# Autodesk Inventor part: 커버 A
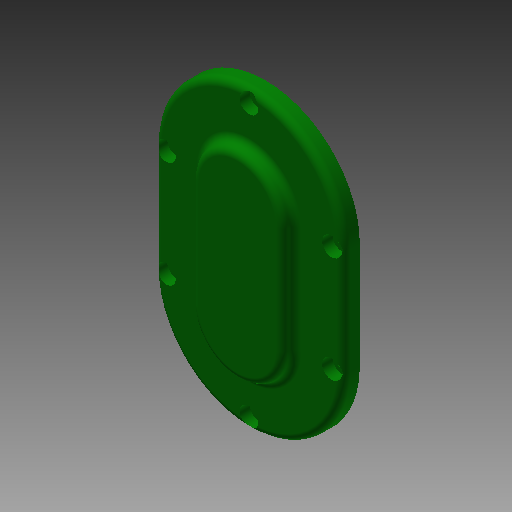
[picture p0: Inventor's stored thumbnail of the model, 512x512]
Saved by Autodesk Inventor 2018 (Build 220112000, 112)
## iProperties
Created: 2020-04
Part Number: 커버 A
Material: 알루미늄 6061
Document SubType Name: Modeling
Designer: mduedu
Density: 2.71 g/cm^3
Mass: 189.426 g
Surface Area: 209.668 cm^2
Volume: 69.8987 cm^3
Appearance: 진녹색
Author: mduedu
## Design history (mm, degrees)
sketch "스케치1"
  geometry: L1 (-40, 0)-(-40, -45); L2 (40, 0)-(40, -45); A1 r 40 centre (0, 0) between (40, 0) and (-40, 0); A2 r 40 centre (0, -45) between (-40, -45) and (40, -45); 1 further point
  constraints: 4 end point, 4 point on circle, 4 tangent, 2 centre point, 1 coincident, 1 equal radius, 1 vertical alignment
  dimensions: "d0" = 80 diameter of A1; "d31" = 45 distance of point (0, 0) A2.centre
extrude "돌출1" new body sketch "스케치1" distance "d1" = 7; taper "d2" = 0 deg
fillet "모깎기2" dims "d7" = 3
sketch "스케치4"
  geometry: L1 (30, 0)-(30, -45); L2 (-30, 0)-(-30, -45); A1 r 30 centre (0, 0) between (30, 0) and (-30, 0); A2 r 30 centre (0, -45) between (-30, -45) and (30, -45); 1 further point
  constraints: 4 end point, 4 point on circle, 4 tangent, 2 centre point, 1 coincident, 1 equal radius, 1 vertical alignment
  dimensions: "d19" = 60 diameter of A1; "d38" = 45 distance of point (0, 0) A2.centre
extrude "돌출3" join sketch "스케치4" distance "d20" = 4; taper "d21" = 0 deg
sketch "스케치7"
  geometry: L1 (-20, 0)-(-20, -45); L2 (20, 0)-(20, -45); A1 r 20 centre (0, 0) between (20, 0) and (-20, 0); A2 r 20 centre (0, -45) between (-20, -45) and (20, -45); 1 further point
  constraints: 4 end point, 4 point on circle, 4 tangent, 2 centre point, 1 coincident, 1 equal radius, 1 vertical alignment
  dimensions: "d45" = 40 diameter of A1; "d47" = 45 distance of point (0, 0) A2.centre
extrude "돌출5" join sketch "스케치7" distance "d48" = 5; taper "d49" = -15 deg
fillet "모깎기4" dims "d50" = 3
chamfer "모따기2" distance "d58" = 1; stored, may be unused: second distance "d59" = 2, angle "d60" = 45 deg
sketch "스케치6"
  geometry: L1 (0, 7)-(37, 7) reference; L2 (0, -4)-(30, -4) reference; L3 (0, -4)-(0, 8); L4 (0, 8)-(8, 8); L5 (11, 5)-(11, 5); L6 (11, 5)-(16, 5); L7 (16, 5)-(16, -4); L8 (-45, -4)-(-45, 8); L9 (-45, 8)-(-37, 8); L10 (-34, 5)-(-34, 4); L11 (-34, 4)-(-31, 4); L12 (-31, 4)-(-31, -4); L13 (-31, -4)-(-45, -4); A1 r 3 centre (8, 5) between (11, 5) and (8, 8); A2 r 3 centre (-37, 5) between (-34, 5) and (-37, 8); 3 further points
  constraints: 22 end point, 5 parallel, 5 point on line, 4 perpendicular, 4 point on circle, 4 tangent, 2 centre point, 2 horizontal alignment, 1 horizontal, 1 vertical
  dimensions: "d39" = 32 diameter of L7 L3; "d41" = 3 distance of point (11, 8) L5.end; "d42" = 9 distance of L6.end L7.end; "d43" = 22 diameter of L5 L3; "d44" = 3 radius of A1; "d51" = 8 distance of L11.end L12.end; "d52" = 45 distance of L2.start L8.start; "d53" = 28 diameter of L12 L8; "d54" = 22 diameter of L10 L8; "d55" = 3 radius of A2
revolve "회전1" stored, may be unused: angle "d56" = 90 deg
revolve "회전2" stored, may be unused: angle "d57" = 90 deg
sketch "스케치3"
  geometry: A1 r 35 centre (0, 0) between (0, 35) and (-35, 0); A2 r 35 centre (0, -45) between (-35, -45) and (0, -80); 3 further points
  constraints: 6 point on circle, 5 vertical alignment, 2 centre point, 2 horizontal alignment, 1 coincident, 1 equal radius
  dimensions: "d8" = 70 diameter of A1; "d69" = 45 distance of point (0, 0) A2.centre
hole "구멍1" sketch "스케치3" at (0, 35), (-35, 0), (-35, -45), (0, -80), (35, -45), (35, 0) diameter "d9" = 4.5; stored, may be unused: countersink angle "d13" = 90 deg, drill point angle "d15" = 118 deg; dims "d10" = 6, "d11" = 8, "d12" = 4.4, "d14" = 8
fillet "모깎기5" dims "d70" = 0.3
chamfer "모따기3" distance "d71" = 1; stored, may be unused: second distance "d72" = 2, angle "d73" = 45 deg
node "솔리드1"
